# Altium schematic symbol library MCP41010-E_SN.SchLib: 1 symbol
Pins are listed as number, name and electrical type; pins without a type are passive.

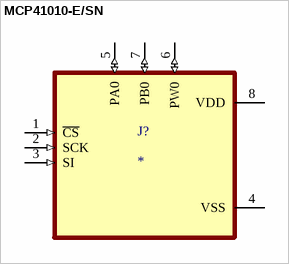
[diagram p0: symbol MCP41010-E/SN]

## MCP41010-E/SN
designator J?
MP: MCP41010-E/SN
footprint MCP41010-E_SN
pins: 1 ~{CS} (in), 2 SCK (in), 3 SI (in), 4 VSS (power), 5 PA0 (io), 6 PW0 (io), 7 PB0 (io), 8 VDD (power)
